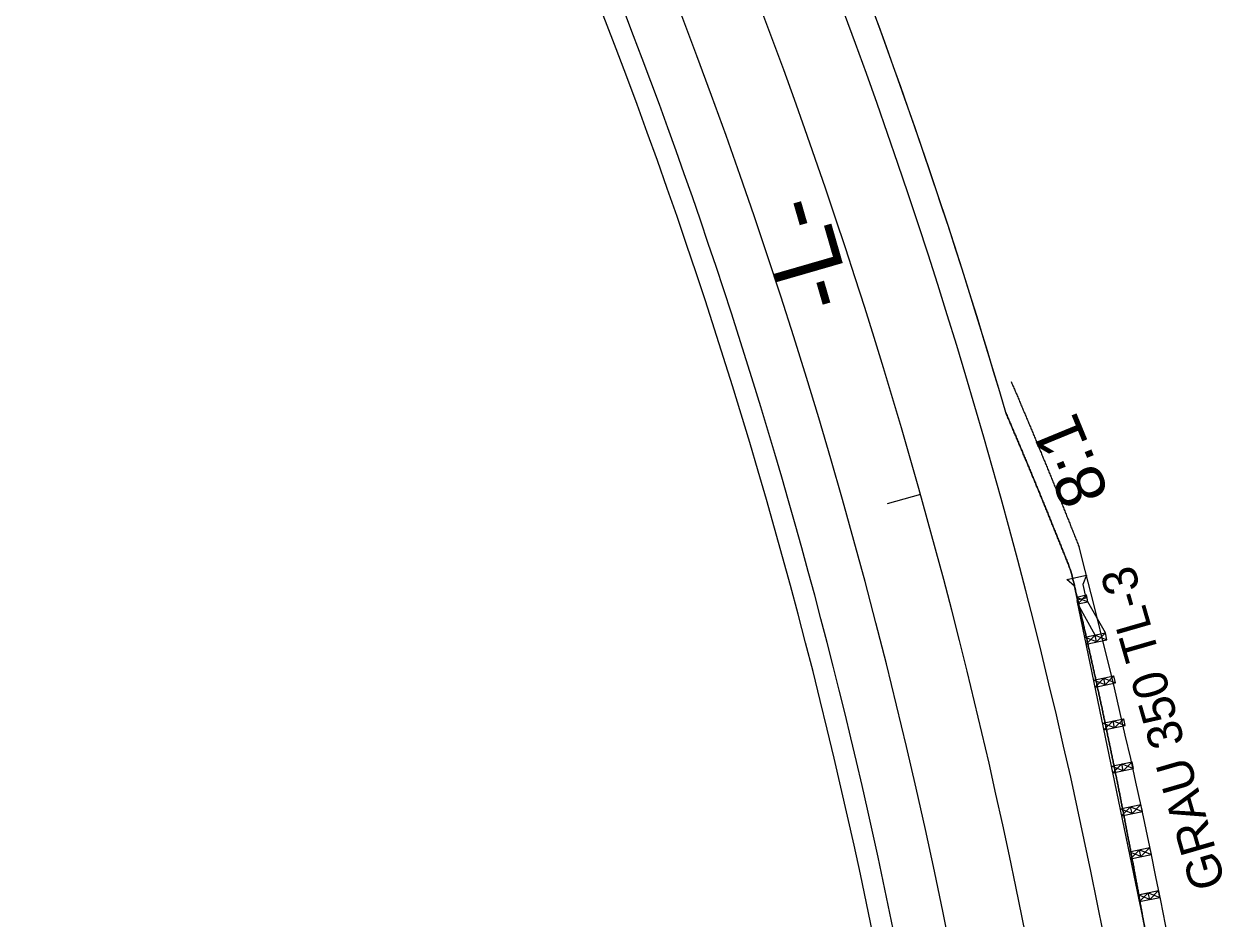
# Model space of a CAD drawing. Extents: x 2167182 to 2168576, y 842635 to 844493.
# Drawn here: x 2167877.5 to 2168050.4, y 843669.8 to 843798.4 of the extents above; entities that cross this region are included whole.
import ezdxf

# ---------------------------------------------------------------- set-up
doc = ezdxf.new("R2010")
doc.units = 0
for name, color, linetype in [('Old_Level_2', 7, 'Continuous'), ('Prop Dimension Text', 7, 'Continuous'), ('Prop EOT', 7, 'Continuous'), ('Prop Guardrail', 7, 'Continuous'), ('Prop Guardrail Anchor Unit CELL', 7, 'Continuous'), ('Prop Horizontal Alignment', 7, 'Continuous'), ('Prop Horizontal Alignment Tick Small', 7, 'Continuous'), ('Prop Paved Shoulder', 7, 'Continuous'), ('Prop Shade Light', 7, 'Continuous'), ('Scratch_Level_1', 7, 'Continuous')]:
    doc.layers.add(name, color=color, linetype=linetype)

msp = doc.modelspace()

# ---------------------------------------------------------------- linework, layer by layer
at = {"layer": 'Prop EOT'}
for radius, end in [(844, 47.10916), (822, 34.57168)]:
    msp.add_arc((2167204.29, 843506.02), radius, 7.27898, end, dxfattribs=at)
at = {"layer": 'Prop Guardrail'}
msp.add_arc((2167204.29, 843506.02), 814.5, 7.27898, 23.14692, dxfattribs=at)
for points in [[(2168038.36, 843669.81), (2168038.24, 843670.49), (2168038.12, 843671.17), (2168037.99, 843671.85), (2168037.87, 843672.53), (2168037.75, 843673.21), (2168037.63, 843673.89), (2168037.51, 843674.57), (2168037.38, 843675.24), (2168037.26, 843675.92), (2168037.13, 843676.6), (2168037.01, 843677.28), (2168036.88, 843677.96), (2168036.75, 843678.64), (2168036.63, 843679.31), (2168036.5, 843679.99), (2168036.37, 843680.67), (2168036.24, 843681.35), (2168036.11, 843682.02), (2168035.98, 843682.7), (2168035.85, 843683.38), (2168035.72, 843684.06), (2168035.59, 843684.73), (2168035.46, 843685.41), (2168035.33, 843686.09), (2168035.19, 843686.76), (2168035.06, 843687.44), (2168034.93, 843688.12), (2168034.79, 843688.79), (2168034.66, 843689.47), (2168034.52, 843690.15), (2168034.38, 843690.82), (2168034.25, 843691.5), (2168034.11, 843692.18), (2168033.97, 843692.85), (2168033.83, 843693.53), (2168033.69, 843694.2), (2168033.55, 843694.88), (2168033.41, 843695.55), (2168033.27, 843696.23), (2168033.13, 843696.91), (2168032.99, 843697.58), (2168032.85, 843698.26), (2168032.7, 843698.93), (2168032.56, 843699.61), (2168032.42, 843700.28), (2168032.27, 843700.96), (2168032.13, 843701.63), (2168031.98, 843702.31), (2168031.83, 843702.98), (2168031.69, 843703.65), (2168031.54, 843704.33), (2168031.39, 843705), (2168031.24, 843705.68), (2168031.09, 843706.35), (2168030.94, 843707.02), (2168030.79, 843707.7), (2168030.64, 843708.37), (2168030.49, 843709.04), (2168030.34, 843709.72), (2168030.19, 843710.39), (2168030.03, 843711.06), (2168029.88, 843711.74), (2168029.73, 843712.41), (2168029.57, 843713.08), (2168029.42, 843713.76), (2168029.26, 843714.43), (2168029.11, 843715.1), (2168028.95, 843715.77), (2168028.79, 843716.44), (2168028.63, 843717.12), (2168028.48, 843717.79), (2168028.32, 843718.46), (2168028, 843719.8)], [(2168046.58, 843615.18), (2168046.49, 843615.93), (2168046.4, 843616.67), (2168046.31, 843617.41), (2168046.22, 843618.15), (2168046.13, 843618.89), (2168046.04, 843619.63), (2168045.95, 843620.37), (2168045.86, 843621.11), (2168045.77, 843621.85), (2168045.67, 843622.59), (2168045.58, 843623.33), (2168045.48, 843624.07), (2168045.39, 843624.81), (2168045.29, 843625.56), (2168045.2, 843626.3), (2168045.1, 843627.04), (2168045, 843627.78), (2168044.9, 843628.52), (2168044.8, 843629.26), (2168044.71, 843630), (2168044.6, 843630.74), (2168044.5, 843631.47), (2168044.4, 843632.21), (2168044.3, 843632.95), (2168044.2, 843633.69), (2168044.09, 843634.43), (2168043.99, 843635.17), (2168043.88, 843635.91), (2168043.78, 843636.65), (2168043.67, 843637.39), (2168043.57, 843638.13), (2168043.46, 843638.87), (2168043.35, 843639.61), (2168043.24, 843640.34), (2168043.13, 843641.08), (2168043.02, 843641.82), (2168042.91, 843642.56), (2168042.8, 843643.3), (2168042.69, 843644.04), (2168042.57, 843644.77), (2168042.46, 843645.51), (2168042.35, 843646.25), (2168042.23, 843646.99), (2168042.12, 843647.73), (2168042, 843648.46), (2168041.88, 843649.2), (2168041.77, 843649.94), (2168041.65, 843650.68), (2168041.53, 843651.41), (2168041.41, 843652.15), (2168041.29, 843652.89), (2168041.17, 843653.63), (2168041.05, 843654.36), (2168040.93, 843655.1), (2168040.81, 843655.84), (2168040.68, 843656.57), (2168040.56, 843657.31), (2168040.43, 843658.05), (2168040.31, 843658.78), (2168040.18, 843659.52), (2168040.06, 843660.25), (2168039.93, 843660.99), (2168039.8, 843661.73), (2168039.67, 843662.46), (2168039.55, 843663.2), (2168039.42, 843663.93), (2168039.29, 843664.67), (2168039.16, 843665.4), (2168039.02, 843666.14), (2168038.89, 843666.87), (2168038.76, 843667.61), (2168038.63, 843668.34), (2168038.36, 843669.81)]]:
    msp.add_spline(points, degree=3, dxfattribs=at)
at = {"layer": 'Prop Guardrail Anchor Unit CELL'}
for p, q in [((2168027.39, 843718.59), (2168030.25, 843719.24)), ((2168028.49, 843717.64), (2168027.39, 843718.59)), ((2168030.25, 843719.24), (2168029.68, 843717.9)), ((2168029.68, 843717.9), (2168030.13, 843715.91)), ((2168028.94, 843715.64), (2168028.49, 843717.64)), ((2168028.77, 843716.08), (2168030.24, 843716.39)), ((2168028.77, 843716.08), (2168030.44, 843715.41)), ((2168030.24, 843716.39), (2168028.97, 843715.1)), ((2168030.44, 843715.41), (2168030.24, 843716.39)), ((2168038.36, 843669.81), (2168028.87, 843715.59)), ((2168029.53, 843715.77), (2168028.94, 843715.64)), ((2168028.97, 843715.1), (2168030.44, 843715.41)), ((2168031.47, 843710.62), (2168028.97, 843715.1)), ((2168030.13, 843715.91), (2168029.53, 843715.77)), ((2168030.44, 843715.41), (2168030.34, 843715.9)), ((2168032.97, 843710.93), (2168030.44, 843715.41)), ((2168029.97, 843710.3), (2168032.97, 843710.93)), ((2168032.97, 843710.93), (2168031.67, 843709.64)), ((2168033.17, 843709.95), (2168032.97, 843710.93)), ((2168031.67, 843709.64), (2168029.97, 843710.3)), ((2168030.17, 843709.32), (2168031.47, 843710.62)), ((2168030.17, 843709.32), (2168033.17, 843709.95)), ((2168031.67, 843709.64), (2168031.47, 843710.62)), ((2168031.47, 843710.62), (2168033.17, 843709.95)), ((2168031.24, 843704.13), (2168034.18, 843704.74)), ((2168032.92, 843703.46), (2168031.24, 843704.13)), ((2168031.45, 843703.15), (2168032.71, 843704.44)), ((2168032.92, 843703.46), (2168032.71, 843704.44)), ((2168032.71, 843704.44), (2168034.38, 843703.76)), ((2168034.18, 843704.74), (2168032.92, 843703.46)), ((2168034.38, 843703.76), (2168034.18, 843704.74)), ((2168031.45, 843703.15), (2168034.38, 843703.76)), ((2168032.52, 843697.96), (2168035.6, 843698.6)), ((2168034.26, 843697.3), (2168032.52, 843697.96)), ((2168032.73, 843696.98), (2168034.06, 843698.28)), ((2168032.73, 843696.98), (2168035.8, 843697.62)), ((2168034.26, 843697.3), (2168034.06, 843698.28)), ((2168034.06, 843698.28), (2168035.8, 843697.62)), ((2168035.6, 843698.6), (2168034.26, 843697.3)), ((2168035.8, 843697.62), (2168035.6, 843698.6)), ((2168033.8, 843691.79), (2168036.77, 843692.41)), ((2168034, 843690.81), (2168035.29, 843692.1)), ((2168035.49, 843691.12), (2168035.29, 843692.1)), ((2168035.29, 843692.1), (2168036.98, 843691.43)), ((2168036.77, 843692.41), (2168035.49, 843691.12)), ((2168036.98, 843691.43), (2168036.77, 843692.41)), ((2168034, 843690.81), (2168033.8, 843691.79)), ((2168035.49, 843691.12), (2168033.8, 843691.79)), ((2168034, 843690.81), (2168036.98, 843691.43)), ((2168035.08, 843685.62), (2168038.06, 843686.24)), ((2168036.78, 843684.95), (2168035.08, 843685.62)), ((2168035.28, 843684.64), (2168036.57, 843685.93)), ((2168035.28, 843684.64), (2168038.27, 843685.26)), ((2168036.78, 843684.95), (2168036.57, 843685.93)), ((2168036.57, 843685.93), (2168038.27, 843685.26)), ((2168038.06, 843686.24), (2168036.78, 843684.95)), ((2168038.27, 843685.26), (2168038.06, 843686.24)), ((2168036.36, 843679.45), (2168039.35, 843680.07)), ((2168036.56, 843678.47), (2168037.85, 843679.76)), ((2168038.06, 843678.78), (2168037.85, 843679.76)), ((2168037.85, 843679.76), (2168039.55, 843679.09)), ((2168039.35, 843680.07), (2168038.06, 843678.78)), ((2168039.55, 843679.09), (2168039.35, 843680.07)), ((2168038.06, 843678.78), (2168036.36, 843679.45)), ((2168036.56, 843678.47), (2168039.55, 843679.09)), ((2168037.64, 843673.28), (2168040.57, 843673.89)), ((2168037.64, 843673.28), (2168039.11, 843673.59)), ((2168037.84, 843672.3), (2168037.64, 843673.28)), ((2168039.31, 843672.61), (2168037.64, 843673.28)), ((2168039.11, 843673.59), (2168037.84, 843672.3)), ((2168037.84, 843672.3), (2168040.78, 843672.91)), ((2168039.31, 843672.61), (2168039.11, 843673.59)), ((2168039.11, 843673.59), (2168040.78, 843672.91)), ((2168040.57, 843673.89), (2168039.31, 843672.61)), ((2168040.78, 843672.91), (2168040.57, 843673.89))]:
    msp.add_line(p, q, dxfattribs=at)
at = {"layer": 'Prop Horizontal Alignment'}
msp.add_arc((2167204.29, 843506.02), 833, 7.27898, 47.10916, dxfattribs=at)
at = {"layer": 'Prop Horizontal Alignment Tick Small'}
msp.add_line((2168006.38, 843730.83), (2168001.56, 843729.48), dxfattribs=at)
at = {"layer": 'Prop Paved Shoulder'}
msp.add_arc((2167204.29, 843506.02), 848, 16.19989, 29.48474, dxfattribs=at)
msp.add_spline([(2168028, 843719.8), (2168027.87, 843720.11), (2168027.75, 843720.42), (2168027.63, 843720.74), (2168027.51, 843721.05), (2168027.38, 843721.36), (2168027.26, 843721.67), (2168027.14, 843721.98), (2168027.01, 843722.29), (2168026.89, 843722.6), (2168026.77, 843722.91), (2168026.64, 843723.22), (2168026.52, 843723.53), (2168026.39, 843723.84), (2168026.27, 843724.15), (2168026.15, 843724.45), (2168026.02, 843724.76), (2168025.9, 843725.07), (2168025.77, 843725.38), (2168025.65, 843725.69), (2168025.52, 843726), (2168025.4, 843726.31), (2168025.27, 843726.62), (2168025.15, 843726.93), (2168025.02, 843727.24), (2168024.9, 843727.55), (2168024.77, 843727.86), (2168024.65, 843728.17), (2168024.52, 843728.47), (2168024.4, 843728.78), (2168024.27, 843729.09), (2168024.14, 843729.4), (2168024.02, 843729.71), (2168023.89, 843730.02), (2168023.77, 843730.33), (2168023.64, 843730.63), (2168023.51, 843730.94), (2168023.39, 843731.25), (2168023.26, 843731.56), (2168023.13, 843731.87), (2168023, 843732.17), (2168022.88, 843732.48), (2168022.75, 843732.79), (2168022.62, 843733.1), (2168022.49, 843733.41), (2168022.37, 843733.71), (2168022.24, 843734.02), (2168022.11, 843734.33), (2168021.98, 843734.64), (2168021.86, 843734.94), (2168021.73, 843735.25), (2168021.6, 843735.56), (2168021.47, 843735.87), (2168021.34, 843736.17), (2168021.21, 843736.48), (2168021.08, 843736.79), (2168020.96, 843737.09), (2168020.83, 843737.4), (2168020.7, 843737.71), (2168020.57, 843738.01), (2168020.44, 843738.32), (2168020.31, 843738.63), (2168020.18, 843738.93), (2168020.05, 843739.24), (2168019.92, 843739.55), (2168019.79, 843739.85), (2168019.66, 843740.16), (2168019.53, 843740.47), (2168019.4, 843740.77), (2168019.27, 843741.08), (2168019.14, 843741.38), (2168019.01, 843741.69), (2168018.88, 843742), (2168018.62, 843742.61)], degree=3, dxfattribs=at)
at = {"layer": 'Prop Shade Light'}
for radius, start, end in [(848, 16.19989, 47.10916), (844, 7.27898, 47.10916), (822, 7.27898, 34.57168), (814.5, 7.27898, 23.14692)]:
    msp.add_arc((2167204.29, 843506.02), radius, start, end, dxfattribs=at)
for points in [[(2168018.62, 843742.61), (2168018.88, 843742), (2168019.01, 843741.69), (2168019.14, 843741.38), (2168019.27, 843741.08), (2168019.4, 843740.77), (2168019.53, 843740.47), (2168019.66, 843740.16), (2168019.79, 843739.85), (2168019.92, 843739.55), (2168020.05, 843739.24), (2168020.18, 843738.93), (2168020.31, 843738.63), (2168020.44, 843738.32), (2168020.57, 843738.01), (2168020.7, 843737.71), (2168020.83, 843737.4), (2168020.96, 843737.09), (2168021.08, 843736.79), (2168021.21, 843736.48), (2168021.34, 843736.17), (2168021.47, 843735.87), (2168021.6, 843735.56), (2168021.73, 843735.25), (2168021.86, 843734.94), (2168021.98, 843734.64), (2168022.11, 843734.33), (2168022.24, 843734.02), (2168022.37, 843733.71), (2168022.49, 843733.41), (2168022.62, 843733.1), (2168022.75, 843732.79), (2168022.88, 843732.48), (2168023, 843732.17), (2168023.13, 843731.87), (2168023.26, 843731.56), (2168023.39, 843731.25), (2168023.51, 843730.94), (2168023.64, 843730.63), (2168023.77, 843730.33), (2168023.89, 843730.02), (2168024.02, 843729.71), (2168024.14, 843729.4), (2168024.27, 843729.09), (2168024.4, 843728.78), (2168024.52, 843728.47), (2168024.65, 843728.17), (2168024.77, 843727.86), (2168024.9, 843727.55), (2168025.02, 843727.24), (2168025.15, 843726.93), (2168025.27, 843726.62), (2168025.4, 843726.31), (2168025.52, 843726), (2168025.65, 843725.69), (2168025.77, 843725.38), (2168025.9, 843725.07), (2168026.02, 843724.76), (2168026.15, 843724.45), (2168026.27, 843724.15), (2168026.39, 843723.84), (2168026.52, 843723.53), (2168026.64, 843723.22), (2168026.77, 843722.91), (2168026.89, 843722.6), (2168027.01, 843722.29), (2168027.14, 843721.98), (2168027.26, 843721.67), (2168027.38, 843721.36), (2168027.51, 843721.05), (2168027.63, 843720.74), (2168027.75, 843720.42), (2168027.87, 843720.11), (2168028, 843719.8)], [(2168028, 843719.8), (2168028.32, 843718.46), (2168028.48, 843717.79), (2168028.63, 843717.12), (2168028.79, 843716.44), (2168028.95, 843715.77), (2168029.11, 843715.1), (2168029.26, 843714.43), (2168029.42, 843713.76), (2168029.57, 843713.08), (2168029.73, 843712.41), (2168029.88, 843711.74), (2168030.03, 843711.06), (2168030.19, 843710.39), (2168030.34, 843709.72), (2168030.49, 843709.04), (2168030.64, 843708.37), (2168030.79, 843707.7), (2168030.94, 843707.02), (2168031.09, 843706.35), (2168031.24, 843705.68), (2168031.39, 843705), (2168031.54, 843704.33), (2168031.69, 843703.65), (2168031.83, 843702.98), (2168031.98, 843702.31), (2168032.13, 843701.63), (2168032.27, 843700.96), (2168032.42, 843700.28), (2168032.56, 843699.61), (2168032.7, 843698.93), (2168032.85, 843698.26), (2168032.99, 843697.58), (2168033.13, 843696.91), (2168033.27, 843696.23), (2168033.41, 843695.55), (2168033.55, 843694.88), (2168033.69, 843694.2), (2168033.83, 843693.53), (2168033.97, 843692.85), (2168034.11, 843692.18), (2168034.25, 843691.5), (2168034.38, 843690.82), (2168034.52, 843690.15), (2168034.66, 843689.47), (2168034.79, 843688.79), (2168034.93, 843688.12), (2168035.06, 843687.44), (2168035.19, 843686.76), (2168035.33, 843686.09), (2168035.46, 843685.41), (2168035.59, 843684.73), (2168035.72, 843684.06), (2168035.85, 843683.38), (2168035.98, 843682.7), (2168036.11, 843682.02), (2168036.24, 843681.35), (2168036.37, 843680.67), (2168036.5, 843679.99), (2168036.63, 843679.31), (2168036.75, 843678.64), (2168036.88, 843677.96), (2168037.01, 843677.28), (2168037.13, 843676.6), (2168037.26, 843675.92), (2168037.38, 843675.24), (2168037.51, 843674.57), (2168037.63, 843673.89), (2168037.75, 843673.21), (2168037.87, 843672.53), (2168037.99, 843671.85), (2168038.12, 843671.17), (2168038.24, 843670.49), (2168038.36, 843669.81)], [(2168038.36, 843669.81), (2168038.63, 843668.34), (2168038.76, 843667.61), (2168038.89, 843666.87), (2168039.02, 843666.14), (2168039.16, 843665.4), (2168039.29, 843664.67), (2168039.42, 843663.93), (2168039.55, 843663.2), (2168039.67, 843662.46), (2168039.8, 843661.73), (2168039.93, 843660.99), (2168040.06, 843660.25), (2168040.18, 843659.52), (2168040.31, 843658.78), (2168040.43, 843658.05), (2168040.56, 843657.31), (2168040.68, 843656.57), (2168040.81, 843655.84), (2168040.93, 843655.1), (2168041.05, 843654.36), (2168041.17, 843653.63), (2168041.29, 843652.89), (2168041.41, 843652.15), (2168041.53, 843651.41), (2168041.65, 843650.68), (2168041.77, 843649.94), (2168041.88, 843649.2), (2168042, 843648.46), (2168042.12, 843647.73), (2168042.23, 843646.99), (2168042.35, 843646.25), (2168042.46, 843645.51), (2168042.57, 843644.77), (2168042.69, 843644.04), (2168042.8, 843643.3), (2168042.91, 843642.56), (2168043.02, 843641.82), (2168043.13, 843641.08), (2168043.24, 843640.34), (2168043.35, 843639.61), (2168043.46, 843638.87), (2168043.57, 843638.13), (2168043.67, 843637.39), (2168043.78, 843636.65), (2168043.88, 843635.91), (2168043.99, 843635.17), (2168044.09, 843634.43), (2168044.2, 843633.69), (2168044.3, 843632.95), (2168044.4, 843632.21), (2168044.5, 843631.47), (2168044.6, 843630.74), (2168044.71, 843630), (2168044.8, 843629.26), (2168044.9, 843628.52), (2168045, 843627.78), (2168045.1, 843627.04), (2168045.2, 843626.3), (2168045.29, 843625.56), (2168045.39, 843624.81), (2168045.48, 843624.07), (2168045.58, 843623.33), (2168045.67, 843622.59), (2168045.77, 843621.85), (2168045.86, 843621.11), (2168045.95, 843620.37), (2168046.04, 843619.63), (2168046.13, 843618.89), (2168046.22, 843618.15), (2168046.31, 843617.41), (2168046.4, 843616.67), (2168046.49, 843615.93), (2168046.58, 843615.18)]]:
    msp.add_spline(points, degree=3, dxfattribs=at)
at = {"layer": 'Scratch_Level_1'}
for radius, end in [(811.5, 26.58604), (853, 14.75546)]:
    msp.add_arc((2167204.29, 843506.02), radius, 7.27898, end, dxfattribs=at)
msp.add_spline([(2168019.39, 843747.08), (2168019.52, 843746.76), (2168019.66, 843746.44), (2168019.8, 843746.12), (2168019.93, 843745.81), (2168020.07, 843745.49), (2168020.21, 843745.17), (2168020.34, 843744.85), (2168020.48, 843744.53), (2168020.61, 843744.21), (2168020.75, 843743.89), (2168020.88, 843743.57), (2168021.02, 843743.25), (2168021.15, 843742.93), (2168021.29, 843742.61), (2168021.42, 843742.29), (2168021.56, 843741.97), (2168021.69, 843741.65), (2168021.83, 843741.33), (2168021.96, 843741.01), (2168022.1, 843740.69), (2168022.23, 843740.37), (2168022.36, 843740.05), (2168022.5, 843739.72), (2168022.63, 843739.4), (2168022.76, 843739.08), (2168022.9, 843738.76), (2168023.03, 843738.44), (2168023.16, 843738.12), (2168023.3, 843737.8), (2168023.43, 843737.48), (2168023.56, 843737.16), (2168023.7, 843736.84), (2168023.83, 843736.51), (2168023.96, 843736.19), (2168024.09, 843735.87), (2168024.23, 843735.55), (2168024.36, 843735.23), (2168024.49, 843734.91), (2168024.62, 843734.58), (2168024.75, 843734.26), (2168024.88, 843733.94), (2168025.02, 843733.62), (2168025.15, 843733.3), (2168025.28, 843732.97), (2168025.41, 843732.65), (2168025.54, 843732.33), (2168025.67, 843732.01), (2168025.8, 843731.69), (2168025.93, 843731.36), (2168026.06, 843731.04), (2168026.19, 843730.72), (2168026.32, 843730.39), (2168026.45, 843730.07), (2168026.58, 843729.75), (2168026.71, 843729.43), (2168026.84, 843729.1), (2168026.97, 843728.78), (2168027.1, 843728.46), (2168027.23, 843728.13), (2168027.36, 843727.81), (2168027.49, 843727.49), (2168027.62, 843727.16), (2168027.75, 843726.84), (2168027.88, 843726.52), (2168028, 843726.19), (2168028.13, 843725.87), (2168028.26, 843725.55), (2168028.39, 843725.22), (2168028.52, 843724.9), (2168028.65, 843724.57), (2168028.77, 843724.25), (2168028.9, 843723.93), (2168029.16, 843723.28)], degree=3, dxfattribs=at)

# ---------------------------------------------------------------- texts
at = {"layer": 'Old_Level_2'}
msp.add_text('-L-', height=10, rotation=106.1263, dxfattribs=at).set_placement((2167996.74, 843758.76))
at = {"layer": 'Prop Dimension Text'}
msp.add_text('8:1', height=7, rotation=112.362, dxfattribs=at).set_placement((2168033.57, 843730.87))
at = {"layer": 'Prop Guardrail Anchor Unit CELL'}
msp.add_text('GRAU 350 TL-3', height=5, rotation=106.1236, dxfattribs=at).set_placement((2168050.27, 843674.85))

doc.saveas('drawing.dxf')
